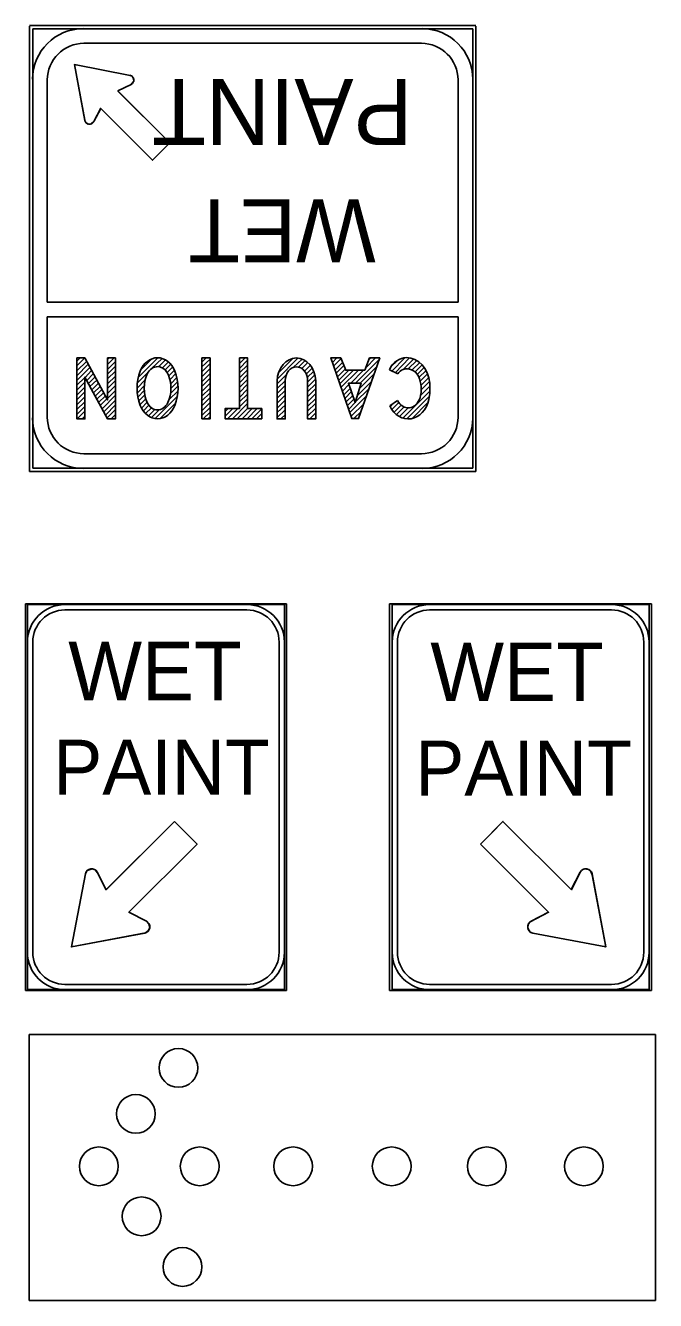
# Model space of a CAD drawing. Extents: x 1531.71 to 1538.58, y 1529.59 to 1539.48.
# Drawn here: x 1537.052 to 1538.152, y 1536.942 to 1539.17 of the extents above; entities that cross this region are included whole.
import ezdxf

# ---------------------------------------------------------------- set-up
doc = ezdxf.new("R2010")
doc.units = 0
doc.layers.add('DETL-LINE', color=7, linetype='Continuous')
doc.layers.add('USER-BORD', color=7, linetype='Continuous')

# ---------------------------------------------------------------- blocks, each defined once
blk = doc.blocks.new('AP1')
at = {"layer": 'USER-BORD'}
for p, q in [((-0.0005, -0.0035), (-0.0005, -0.5033)), ((1.1745, -0.0035), (-0.0005, -0.0035)), ((0.1953, -0.0035), (0.1953, -0.0035)), ((0.3911, -0.0035), (0.3911, -0.0035)), ((0.587, -0.0035), (0.587, -0.0035)), ((0.7828, -0.0035), (0.7828, -0.0035)), ((0.9787, -0.0035), (0.9787, -0.0035)), ((1.1745, -0.5033), (1.1745, -0.0035)), ((-0.0005, -0.5033), (1.1745, -0.5033))]:
    blk.add_line(p, q, dxfattribs=at)
for centre in [(0.2793, -0.0665), (0.1995, -0.1528), (0.13, -0.2513), (0.3192, -0.2513), (0.4945, -0.2513), (0.6795, -0.2513), (0.858, -0.2513), (1.0402, -0.2513), (0.2103, -0.3452), (0.2869, -0.4403)]:
    blk.add_circle(centre, 0.0364, dxfattribs=at)
blk = doc.blocks.new('EBK780')
at = {"layer": 'USER-BORD'}
blk.add_lwpolyline([(1.5, 0), (0.39, 1.65), (0.39, 0), (0, 0), (0, 2.4), (0.39, 2.4), (1.5, 0.75), (1.5, 2.4), (1.89, 2.4), (1.89, 0)], close=True, dxfattribs=at)
blk = doc.blocks.new('EBK790')
at = {"layer": 'USER-BORD'}
for centre, radius, start, end in [((1, 1.451), 0.943, 26.0505, 153.9495), ((1, 1.451), 0.593, 30.8734, 149.1266), ((1.477, 1.193), 1.484, 153.1125, 206.8875), ((1.477, 1.193), 1.134, 150.334, 206.8875), ((0.523, 1.193), 1.134, 330.334, 29.666), ((0.523, 1.193), 1.484, 333.1125, 26.8875), ((1, 0.936), 0.943, 206.0505, 333.9495), ((1, 0.936), 0.593, 206.0505, 329.1266)]:
    blk.add_arc(centre, radius, start, end, dxfattribs=at)
blk = doc.blocks.new('EBK730')
at = {"layer": 'USER-BORD'}
blk.add_lwpolyline([(0.3996, 2.3977), (0.3996, 0), (0, 0), (0, 2.3977)], close=True, dxfattribs=at)
blk = doc.blocks.new('EBK840')
at = {"layer": 'USER-BORD'}
blk.add_lwpolyline([(1.1024, -0.0068), (0.7028, -0.0068), (0.7028, 1.9913), (0.0026, 1.9913), (0.0026, 2.3909), (1.8026, 2.3909), (1.8026, 1.9913), (1.1024, 1.9913)], close=True, dxfattribs=at)
blk = doc.blocks.new('EBK850')
at = {"layer": 'USER-BORD'}
for points in [[(0.001, 0.9), (0.001, 2.398), (0.401, 2.398), (0.401, 0.9)], [(1.501, 0.9), (1.501, 2.398), (1.901, 2.398), (1.901, 0.9)]]:
    blk.add_lwpolyline(points, dxfattribs=at)
for centre, radius, start, end in [((0.951, 0.951), 0.951, 183.0846, 356.9154), ((0.951, 0.9), 0.55, 180, 0)]:
    blk.add_arc(centre, radius, start, end, dxfattribs=at)
blk = doc.blocks.new('EBK650')
at = {"layer": 'USER-BORD'}
blk.add_lwpolyline([(1.6744, 0.479), (0.7349, 0.479), (0.4957, 0), (0, 0), (1.0352, 2.3825), (1.3681, 2.3825), (2.4033, 0), (1.9076, 0), (1.6684, 0.479)], dxfattribs=at)
blk.add_lwpolyline([(1.2017, 1.7541), (0.9085, 0.9938), (1.5306, 0.9938)], close=True, dxfattribs=at)
blk = doc.blocks.new('EBK670')
at = {"layer": 'USER-BORD'}
for p, q in [((1.582, 1.676), (1.964, 1.888)), ((1.981, 0.462), (1.569, 0.631)), ((1.981, 0.462), (1.981, 0.462))]:
    blk.add_line(p, q, dxfattribs=at)
for centre, radius, start, end in [((1.058, 1.338), 1.06, 31.2566, 163.719), ((2.007, 1.189), 2.016, 167.2133, 185.6844), ((1.445, 1.229), 1.023, 160.6047, 209.6938), ((1.058, 1.338), 0.623, 32.8208, 158.2531), ((1.124, 1.121), 1.131, 186.6798, 270.8634), ((1.124, 1.121), 0.695, 215.044, 285.8113), ((1.148, 0.961), 0.535, 288.0047, 321.8072), ((1.148, 0.961), 0.971, 269.5882, 329.0756)]:
    blk.add_arc(centre, radius, start, end, dxfattribs=at)

msp = doc.modelspace()

# ---------------------------------------------------------------- linework, layer by layer
at = {"layer": 'DETL-LINE'}
for p, q in [((1537.8382, 1539.1696), (1537.059, 1539.1696)), ((1537.059, 1538.3904), (1537.059, 1539.1682)), ((1537.1528, 1539.1639), (1537.0648, 1539.1639)), ((1537.0648, 1539.0759), (1537.0648, 1539.1639)), ((1537.1528, 1539.1639), (1537.7445, 1539.1639)), ((1537.7445, 1539.1639), (1537.8329, 1539.1639)), ((1537.8329, 1539.0759), (1537.8329, 1539.1639)), ((1537.8382, 1538.3904), (1537.8382, 1539.1682)), ((1537.743, 1539.1385), (1537.1542, 1539.1385)), ((1537.1375, 1539.1012), (1537.1556, 1539.0041)), ((1537.1375, 1539.1012), (1537.2346, 1539.0825)), ((1537.0648, 1538.4841), (1537.0648, 1539.0759)), ((1537.0901, 1539.0744), (1537.0901, 1538.686)), ((1537.8071, 1538.686), (1537.8071, 1539.0744)), ((1537.8329, 1539.0759), (1537.8329, 1538.4841)), ((1537.2135, 1539.0553), (1537.2365, 1539.0668)), ((1537.2135, 1539.0548), (1537.3039, 1538.9644)), ((1537.1834, 1539.0251), (1537.1714, 1539.0017)), ((1537.1834, 1539.0247), (1537.2738, 1538.9343)), ((1537.2738, 1538.9343), (1537.3039, 1538.9644)), ((1537.0901, 1538.686), (1537.8071, 1538.686)), ((1537.8071, 1538.6607), (1537.0901, 1538.6607)), ((1537.0901, 1538.4856), (1537.0901, 1538.6607)), ((1537.8071, 1538.6607), (1537.8071, 1538.4856)), ((1537.8072, 1538.4855), (1537.8071, 1538.6607)), ((1537.1556, 1538.5889), (1537.1417, 1538.575)), ((1537.1475, 1538.5889), (1537.1417, 1538.5831)), ((1537.159, 1538.5831), (1537.1417, 1538.5664)), ((1537.1618, 1538.5779), (1537.1417, 1538.5578)), ((1537.2068, 1538.5889), (1537.1954, 1538.5774)), ((1537.1982, 1538.5889), (1537.1954, 1538.5861)), ((1537.2092, 1538.5827), (1537.1954, 1538.5688)), ((1537.2829, 1538.5889), (1537.2494, 1538.5554)), ((1537.2723, 1538.587), (1537.2542, 1538.5688)), ((1537.2905, 1538.5879), (1537.2723, 1538.5702)), ((1537.2963, 1538.5856), (1537.2843, 1538.5736)), ((1537.3015, 1538.5822), (1537.291, 1538.5717)), ((1537.3058, 1538.5779), (1537.2958, 1538.5679)), ((1537.3675, 1538.5889), (1537.3599, 1538.5813)), ((1537.3742, 1538.587), (1537.3599, 1538.5731)), ((1537.3742, 1538.5789), (1537.3599, 1538.5645)), ((1537.4354, 1538.5889), (1537.4254, 1538.5793)), ((1537.4268, 1538.5889), (1537.4254, 1538.5879)), ((1537.4397, 1538.5851), (1537.4254, 1538.5707)), ((1537.5278, 1538.5889), (1537.4919, 1538.5526)), ((1537.5187, 1538.5879), (1537.4943, 1538.5635)), ((1537.535, 1538.587), (1537.5201, 1538.5727)), ((1537.5402, 1538.5841), (1537.5287, 1538.5727)), ((1537.545, 1538.5808), (1537.5345, 1538.5702)), ((1537.5871, 1538.5889), (1537.5857, 1538.5875)), ((1537.5957, 1538.5889), (1537.588, 1538.5808)), ((1537.6033, 1538.5879), (1537.5899, 1538.5745)), ((1537.6058, 1538.5817), (1537.5924, 1538.5683)), ((1537.6698, 1538.587), (1537.6277, 1538.5444)), ((1537.6631, 1538.5889), (1537.6459, 1538.5717)), ((1537.655, 1538.5889), (1537.6516, 1538.5856)), ((1537.7014, 1538.5846), (1537.6899, 1538.5731)), ((1537.7143, 1538.5889), (1537.6913, 1538.5659)), ((1537.7224, 1538.5889), (1537.6971, 1538.5631)), ((1537.7291, 1538.587), (1537.7105, 1538.5683)), ((1537.7349, 1538.5846), (1537.72, 1538.5697)), ((1537.7402, 1538.5808), (1537.7268, 1538.5679)), ((1537.1647, 1538.5722), (1537.1417, 1538.5492)), ((1537.1676, 1538.5669), (1537.1561, 1538.5549)), ((1537.1705, 1538.5612), (1537.159, 1538.5497)), ((1537.1738, 1538.5559), (1537.1618, 1538.5439)), ((1537.2092, 1538.5745), (1537.1954, 1538.5607)), ((1537.2092, 1538.5659), (1537.1954, 1538.5521)), ((1537.2092, 1538.5573), (1537.1954, 1538.5435)), ((1537.2675, 1538.565), (1537.2474, 1538.5454)), ((1537.3092, 1538.5731), (1537.2996, 1538.5635)), ((1537.312, 1538.5674), (1537.3025, 1538.5578)), ((1537.3144, 1538.5616), (1537.3044, 1538.5511)), ((1537.3742, 1538.5702), (1537.3599, 1538.5559)), ((1537.3742, 1538.5616), (1537.3599, 1538.5473)), ((1537.4397, 1538.5765), (1537.4254, 1538.5626)), ((1537.4397, 1538.5683), (1537.4254, 1538.554)), ((1537.4397, 1538.5597), (1537.4254, 1538.5454)), ((1537.5077, 1538.5602), (1537.4914, 1538.5439)), ((1537.5493, 1538.5765), (1537.5392, 1538.5659)), ((1537.5526, 1538.5712), (1537.5421, 1538.5607)), ((1537.5555, 1538.5655), (1537.544, 1538.5545)), ((1537.5574, 1538.5593), (1537.5445, 1538.5463)), ((1537.6081, 1538.576), (1537.5942, 1538.5621)), ((1537.6105, 1538.5697), (1537.5966, 1538.5559)), ((1537.6167, 1538.5674), (1537.5986, 1538.5497)), ((1537.6249, 1538.5674), (1537.601, 1538.5435)), ((1537.6335, 1538.5674), (1537.6028, 1538.5372)), ((1537.6421, 1538.5674), (1537.6192, 1538.5444)), ((1537.6608, 1538.5612), (1537.6354, 1538.5358)), ((1537.6655, 1538.5741), (1537.6359, 1538.5444)), ((1537.7445, 1538.5769), (1537.732, 1538.5645)), ((1537.7478, 1538.5722), (1537.7358, 1538.5597)), ((1537.7512, 1538.5669), (1537.7387, 1538.5545)), ((1537.754, 1538.5612), (1537.7411, 1538.5483)), ((1537.1556, 1538.5549), (1537.1417, 1538.5411)), ((1537.1556, 1538.5463), (1537.1417, 1538.5325)), ((1537.1556, 1538.5377), (1537.1417, 1538.5238)), ((1537.1767, 1538.5501), (1537.1647, 1538.5387)), ((1537.1795, 1538.5449), (1537.168, 1538.5329)), ((1537.1824, 1538.5392), (1537.171, 1538.5277)), ((1537.1853, 1538.5339), (1537.1738, 1538.5219)), ((1537.2092, 1538.5492), (1537.1954, 1538.5353)), ((1537.2092, 1538.5406), (1537.1954, 1538.5267)), ((1537.2613, 1538.5506), (1537.247, 1538.5363)), ((1537.2599, 1538.5406), (1537.2474, 1538.5281)), ((1537.3164, 1538.5549), (1537.3058, 1538.5439)), ((1537.3187, 1538.5401), (1537.3058, 1538.5272)), ((1537.3178, 1538.5478), (1537.3063, 1538.5363)), ((1537.3742, 1538.5535), (1537.3599, 1538.5392)), ((1537.3742, 1538.5449), (1537.3599, 1538.5305)), ((1537.3742, 1538.5363), (1537.3599, 1538.5219)), ((1537.4397, 1538.5511), (1537.4254, 1538.5372)), ((1537.4397, 1538.543), (1537.4254, 1538.5286)), ((1537.4397, 1538.5344), (1537.4254, 1538.52)), ((1537.5058, 1538.5497), (1537.4914, 1538.5353)), ((1537.5058, 1538.5411), (1537.4914, 1538.5267)), ((1537.5588, 1538.5521), (1537.5445, 1538.5377)), ((1537.5588, 1538.5435), (1537.5445, 1538.5296)), ((1537.5588, 1538.5353), (1537.5445, 1538.521)), ((1537.6167, 1538.5425), (1537.6053, 1538.531)), ((1537.6192, 1538.5363), (1537.6076, 1538.5243)), ((1537.6521, 1538.5353), (1537.6277, 1538.5114)), ((1537.6564, 1538.5483), (1537.6316, 1538.5234)), ((1537.7578, 1538.5397), (1537.7416, 1538.5234)), ((1537.7559, 1538.5545), (1537.7425, 1538.5411)), ((1537.7574, 1538.5478), (1537.7425, 1538.5329)), ((1537.1556, 1538.5296), (1537.1417, 1538.5157)), ((1537.1556, 1538.521), (1537.1417, 1538.5071)), ((1537.1556, 1538.5123), (1537.1417, 1538.4985)), ((1537.1881, 1538.5281), (1537.1767, 1538.5167)), ((1537.1915, 1538.5229), (1537.1795, 1538.511)), ((1537.1944, 1538.5172), (1537.1824, 1538.5057)), ((1537.2092, 1538.5238), (1537.1858, 1538.4999)), ((1537.2092, 1538.5152), (1537.1886, 1538.4947)), ((1537.2092, 1538.5319), (1537.1954, 1538.5181)), ((1537.2594, 1538.5319), (1537.2484, 1538.5205)), ((1537.2604, 1538.5243), (1537.2499, 1538.5138)), ((1537.2623, 1538.5176), (1537.2522, 1538.5076)), ((1537.2647, 1538.5114), (1537.2546, 1538.5014)), ((1537.3178, 1538.5224), (1537.2781, 1538.4827)), ((1537.3149, 1538.511), (1537.2867, 1538.4827)), ((1537.3187, 1538.5315), (1537.303, 1538.5162)), ((1537.3742, 1538.5277), (1537.3599, 1538.5138)), ((1537.3742, 1538.5195), (1537.3599, 1538.5052)), ((1537.3742, 1538.511), (1537.3599, 1538.4966)), ((1537.4397, 1538.5258), (1537.4254, 1538.5119)), ((1537.4397, 1538.5176), (1537.4254, 1538.5033)), ((1537.5058, 1538.5325), (1537.4914, 1538.5186)), ((1537.5058, 1538.5243), (1537.4914, 1538.51)), ((1537.5058, 1538.5157), (1537.4914, 1538.5014)), ((1537.5588, 1538.5267), (1537.5445, 1538.5123)), ((1537.5588, 1538.5181), (1537.5445, 1538.5043)), ((1537.621, 1538.5301), (1537.6096, 1538.5181)), ((1537.6234, 1538.5234), (1537.612, 1538.5119)), ((1537.6258, 1538.5172), (1537.6139, 1538.5057)), ((1537.6277, 1538.511), (1537.6162, 1538.4994)), ((1537.6474, 1538.5224), (1537.6182, 1538.4933)), ((1537.7038, 1538.511), (1537.6913, 1538.4985)), ((1537.7578, 1538.531), (1537.7105, 1538.4837)), ((1537.7574, 1538.5219), (1537.7176, 1538.4822)), ((1537.755, 1538.5114), (1537.7263, 1538.4827)), ((1537.1556, 1538.5043), (1537.1417, 1538.4903)), ((1537.1556, 1538.4956), (1537.1422, 1538.4822)), ((1537.2092, 1538.5067), (1537.1915, 1538.4889)), ((1537.2092, 1538.4985), (1537.1944, 1538.4837)), ((1537.2092, 1538.4899), (1537.2016, 1538.4822)), ((1537.2675, 1538.5062), (1537.258, 1538.4966)), ((1537.2718, 1538.5019), (1537.2618, 1538.4918)), ((1537.2776, 1538.4989), (1537.2666, 1538.488)), ((1537.2852, 1538.4981), (1537.2718, 1538.4847)), ((1537.3742, 1538.5023), (1537.3599, 1538.4885)), ((1537.3742, 1538.4942), (1537.3623, 1538.4822)), ((1537.414, 1538.5004), (1537.4005, 1538.487)), ((1537.4058, 1538.5004), (1537.4005, 1538.4951)), ((1537.4225, 1538.5004), (1537.4048, 1538.4827)), ((1537.4397, 1538.509), (1537.4134, 1538.4827)), ((1537.4397, 1538.5004), (1537.4216, 1538.4827)), ((1537.4479, 1538.5004), (1537.4302, 1538.4827)), ((1537.4565, 1538.5004), (1537.4388, 1538.4827)), ((1537.4646, 1538.4999), (1537.447, 1538.4827)), ((1537.4646, 1538.4918), (1537.4556, 1538.4827)), ((1537.5058, 1538.5071), (1537.4914, 1538.4933)), ((1537.5058, 1538.4989), (1537.4914, 1538.4847)), ((1537.5058, 1538.4903), (1537.4976, 1538.4822)), ((1537.5588, 1538.51), (1537.5445, 1538.4956)), ((1537.5588, 1538.5014), (1537.5445, 1538.487)), ((1537.5588, 1538.4927), (1537.5483, 1538.4822)), ((1537.643, 1538.5095), (1537.6206, 1538.487)), ((1537.6383, 1538.4961), (1537.6249, 1538.4827)), ((1537.6923, 1538.5081), (1537.6885, 1538.5037)), ((1537.7076, 1538.5062), (1537.6952, 1538.4937)), ((1537.7129, 1538.5033), (1537.6995, 1538.4899)), ((1537.7196, 1538.5014), (1537.7048, 1538.4865)), ((1537.0648, 1538.4841), (1537.0648, 1538.3961)), ((1537.1556, 1538.487), (1537.1508, 1538.4822)), ((1537.3742, 1538.4856), (1537.3709, 1538.4822)), ((1537.4646, 1538.4832), (1537.4642, 1538.4827)), ((1537.5588, 1538.4847), (1537.5564, 1538.4822)), ((1537.634, 1538.4832), (1537.6335, 1538.4827)), ((1537.8329, 1538.4841), (1537.8329, 1538.3961)), ((1537.1542, 1538.4215), (1537.743, 1538.4215)), ((1537.8382, 1538.3904), (1537.059, 1538.3904)), ((1537.1528, 1538.3961), (1537.0648, 1538.3961)), ((1537.7445, 1538.3961), (1537.1528, 1538.3961)), ((1537.7445, 1538.3961), (1537.8329, 1538.3961)), ((1537.5074, 1538.1594), (1537.0522, 1538.1594)), ((1537.0522, 1537.4838), (1537.0522, 1538.1594)), ((1537.0557, 1538.0924), (1537.0557, 1538.1579)), ((1537.1212, 1538.1579), (1537.0557, 1538.1579)), ((1537.4385, 1538.1579), (1537.1212, 1538.1579)), ((1537.4385, 1538.1579), (1537.504, 1538.1579)), ((1537.504, 1538.0924), (1537.504, 1538.1579)), ((1537.5074, 1537.5439), (1537.5074, 1538.1594)), ((1538.145, 1538.1594), (1537.6876, 1538.1594)), ((1537.6876, 1537.4838), (1537.6876, 1538.1594)), ((1537.6922, 1538.0924), (1537.6922, 1538.1579)), ((1537.7576, 1538.1579), (1537.6922, 1538.1579)), ((1538.075, 1538.1579), (1537.7576, 1538.1579)), ((1538.075, 1538.1579), (1538.1405, 1538.1579)), ((1538.1106, 1538.1583), (1538.0804, 1538.1583)), ((1538.1106, 1538.1583), (1538.1408, 1538.1583)), ((1538.1405, 1538.0924), (1538.1405, 1538.1579)), ((1538.1408, 1538.1583), (1538.1408, 1538.0044)), ((1538.145, 1537.4838), (1538.145, 1538.1594)), ((1537.1212, 1538.1487), (1537.4385, 1538.1487)), ((1537.7576, 1538.1487), (1538.075, 1538.1487)), ((1537.0557, 1538.0924), (1537.0557, 1537.5507)), ((1537.0649, 1537.5507), (1537.0649, 1538.0924)), ((1537.4948, 1538.0924), (1537.4948, 1537.5507)), ((1537.504, 1537.5507), (1537.504, 1538.0924)), ((1537.6922, 1538.0924), (1537.6922, 1537.5507)), ((1537.7014, 1537.5507), (1537.7014, 1538.0924)), ((1538.1313, 1538.0924), (1538.1313, 1537.5507)), ((1538.1405, 1537.5507), (1538.1405, 1538.0924)), ((1537.1932, 1537.6602), (1537.3122, 1537.7793)), ((1537.3122, 1537.7793), (1537.3516, 1537.7395)), ((1537.8855, 1537.7793), (1537.8461, 1537.7395)), ((1538.0046, 1537.6602), (1537.8855, 1537.7793)), ((1537.2326, 1537.6204), (1537.3516, 1537.7395)), ((1537.9651, 1537.6204), (1537.8461, 1537.7395)), ((1537.1323, 1537.5599), (1537.1568, 1537.6878)), ((1537.1928, 1537.6599), (1537.1775, 1537.6905)), ((1538.005, 1537.6599), (1538.0203, 1537.6905)), ((1538.065, 1537.5599), (1538.041, 1537.6878)), ((1537.2326, 1537.6204), (1537.2632, 1537.6047)), ((1537.9651, 1537.6204), (1537.9345, 1537.6047)), ((1537.1323, 1537.5599), (1537.2602, 1537.584)), ((1538.065, 1537.5599), (1537.9376, 1537.584)), ((1537.0557, 1537.5507), (1537.0557, 1537.4853)), ((1537.504, 1537.5507), (1537.504, 1537.4853)), ((1537.5074, 1537.5439), (1537.5074, 1537.4838)), ((1537.6922, 1537.5507), (1537.6922, 1537.4853)), ((1538.1405, 1537.5507), (1538.1405, 1537.4853)), ((1537.4385, 1537.4945), (1537.1212, 1537.4945)), ((1537.4387, 1537.4945), (1537.4385, 1537.4945)), ((1538.075, 1537.4945), (1537.7576, 1537.4945)), ((1538.0752, 1537.4945), (1538.075, 1537.4945)), ((1537.0522, 1537.4838), (1537.5074, 1537.4838)), ((1537.1212, 1537.4853), (1537.0557, 1537.4853)), ((1537.1212, 1537.4853), (1537.4385, 1537.4853)), ((1537.4385, 1537.4853), (1537.504, 1537.4853)), ((1537.7037, 1537.4838), (1537.6876, 1537.4838)), ((1537.7576, 1537.4853), (1537.6922, 1537.4853)), ((1537.7037, 1537.4838), (1538.0501, 1537.4838)), ((1537.7576, 1537.4853), (1538.075, 1537.4853)), ((1538.0501, 1537.4838), (1538.0804, 1537.4838)), ((1538.1405, 1537.4853), (1538.075, 1537.4853)), ((1538.0804, 1537.4838), (1538.145, 1537.4838))]:
    msp.add_line(p, q, dxfattribs=at)
for points in [[(1537.2365, 1539.0668), (1537.2135, 1539.0553), (1537.3039, 1538.9644), (1537.2738, 1538.9343), (1537.1834, 1539.0247), (1537.1714, 1539.0017), (1537.1668, 1538.9976), (1537.1613, 1538.9975), (1537.1574, 1539.0001), (1537.1556, 1539.0038), (1537.1375, 1539.1012), (1537.2346, 1539.0825), (1537.2382, 1539.0809), (1537.2409, 1539.0767), (1537.241, 1539.0722)], [(1537.3122, 1537.7793), (1537.3516, 1537.7395), (1537.2326, 1537.6204), (1537.2632, 1537.6047), (1537.2677, 1537.6003), (1537.269, 1537.5939), (1537.2671, 1537.5885), (1537.2615, 1537.5845), (1537.1323, 1537.5599), (1537.1568, 1537.6878), (1537.16, 1537.6936), (1537.1686, 1537.6965), (1537.174, 1537.6944), (1537.178, 1537.6894), (1537.1928, 1537.6599)], [(1537.8461, 1537.7395), (1537.8658, 1537.7594), (1537.8855, 1537.7793), (1538.0046, 1537.6602), (1538.0203, 1537.6905), (1538.0269, 1537.6961), (1538.0357, 1537.6951), (1538.0384, 1537.6926), (1538.0412, 1537.6861), (1538.065, 1537.5599), (1537.9376, 1537.584), (1537.9332, 1537.586), (1537.9288, 1537.5927), (1537.9295, 1537.5995), (1537.9332, 1537.6039), (1537.9651, 1537.6204)]]:
    msp.add_lwpolyline(points, close=True, dxfattribs=at)
for centre, radius, start, end in [((1537.1529, 1539.0758), 0.0883, 90, 180), ((1537.7444, 1539.0758), 0.0883, 0, 90), ((1537.1542, 1539.0745), 0.064, 90, 180), ((1537.7431, 1539.0745), 0.064, 0, 90), ((1537.2329, 1539.0744), 0.00838, 297, 79.2603), ((1537.1639, 1539.0054), 0.00838, 190.7397, 333), ((1537.1529, 1538.4842), 0.0883, 180, 270), ((1537.1542, 1538.4855), 0.064, 180, 270), ((1537.7431, 1538.4855), 0.064, 270, 0), ((1537.7444, 1538.4842), 0.0883, 270, 0), ((1537.121, 1538.0925), 0.0654, 90, 180), ((1537.4387, 1538.0925), 0.0654, 0, 90), ((1537.7575, 1538.0925), 0.0654, 90, 180), ((1538.0751, 1538.0925), 0.0654, 0, 90), ((1537.121, 1538.0925), 0.0561, 90, 180), ((1537.4387, 1538.0925), 0.0561, 0, 90), ((1537.7575, 1538.0925), 0.0561, 90, 180), ((1538.0751, 1538.0925), 0.0561, 0, 90), ((1537.1675, 1537.6856), 0.011, 27, 169.2603), ((1538.0302, 1537.6856), 0.011, 10.7397, 153), ((1537.2581, 1537.595), 0.011, 280.7397, 63), ((1537.9396, 1537.595), 0.011, 117, 259.2603), ((1537.121, 1537.5506), 0.0654, 180, 270), ((1537.121, 1537.5506), 0.0561, 180, 270), ((1537.4387, 1537.5506), 0.0654, 270, 0), ((1537.4387, 1537.5506), 0.0561, 270, 0), ((1537.7575, 1537.5506), 0.0654, 180, 270), ((1537.7575, 1537.5506), 0.0561, 180, 270), ((1538.0751, 1537.5506), 0.0654, 270, 0), ((1538.0751, 1537.5506), 0.0561, 270, 0)]:
    msp.add_arc(centre, radius, start, end, dxfattribs=at)

# ---------------------------------------------------------------- block references
at = {"layer": 'DETL-LINE', "xscale": 0.035563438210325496, "yscale": 0.044454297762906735, "rotation": 179.99999999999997}
for name, p in [('EBK780', (1537.2092, 1538.5889)), ('EBK790', (1537.3182, 1538.5889)), ('EBK730', (1537.3742, 1538.5889)), ('EBK840', (1537.4646, 1538.5889)), ('EBK850', (1537.5588, 1538.5889)), ('EBK650', (1537.6703, 1538.5889)), ('EBK670', (1537.7578, 1538.5889))]:
    msp.add_blockref(name, p, dxfattribs=at)
at = {"layer": 'DETL-LINE', "xscale": 0.930070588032, "yscale": 0.930070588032}
msp.add_blockref('AP1', (1537.0593, 1537.4104), dxfattribs=at)

# ---------------------------------------------------------------- texts
at = {"layer": 'DETL-LINE'}
for s, height, rotation, p in [('PAINT', 0.11552, 180, (1537.7276, 1539.0762)), ('WET', 0.10996, 180, (1537.6634, 1538.866)), ('WET', 0.10193, 360, (1537.1268, 1537.991)), ('WET', 0.10193, 360, (1537.7587, 1537.9895)), ('PAINT', 0.09601, 360, (1537.1005, 1537.8258)), ('PAINT', 0.09601, 360, (1537.7324, 1537.8243))]:
    msp.add_text(s, height=height, rotation=rotation, dxfattribs=at).set_placement(p)

doc.saveas('drawing.dxf')
